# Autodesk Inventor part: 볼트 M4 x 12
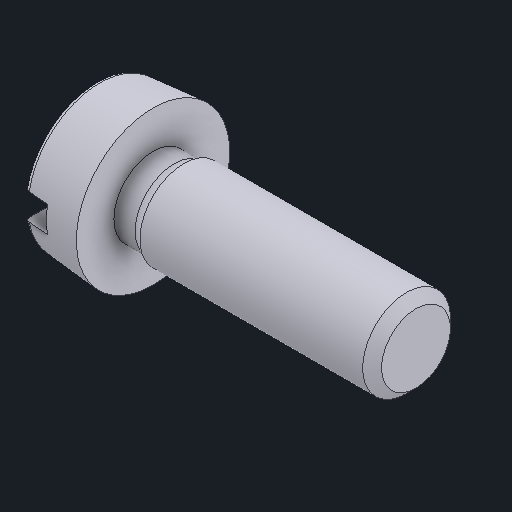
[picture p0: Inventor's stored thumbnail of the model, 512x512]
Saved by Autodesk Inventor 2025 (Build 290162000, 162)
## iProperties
Created: 2025-08
Part Number: 볼트 M4 x 12
Material: 강철, 연강
Description: 6각머리 태핑 나사
Document SubType Name: Modeling
Designer: infra023
Density: 7.85 g/cm^3
Appearance: 기본값
Author: jhkim
Sending System: Autodesk Inventor 2026
Preprocessor: ST-DEVELOPER v20.1
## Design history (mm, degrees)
feature "Solid1"
node "솔리드1"
